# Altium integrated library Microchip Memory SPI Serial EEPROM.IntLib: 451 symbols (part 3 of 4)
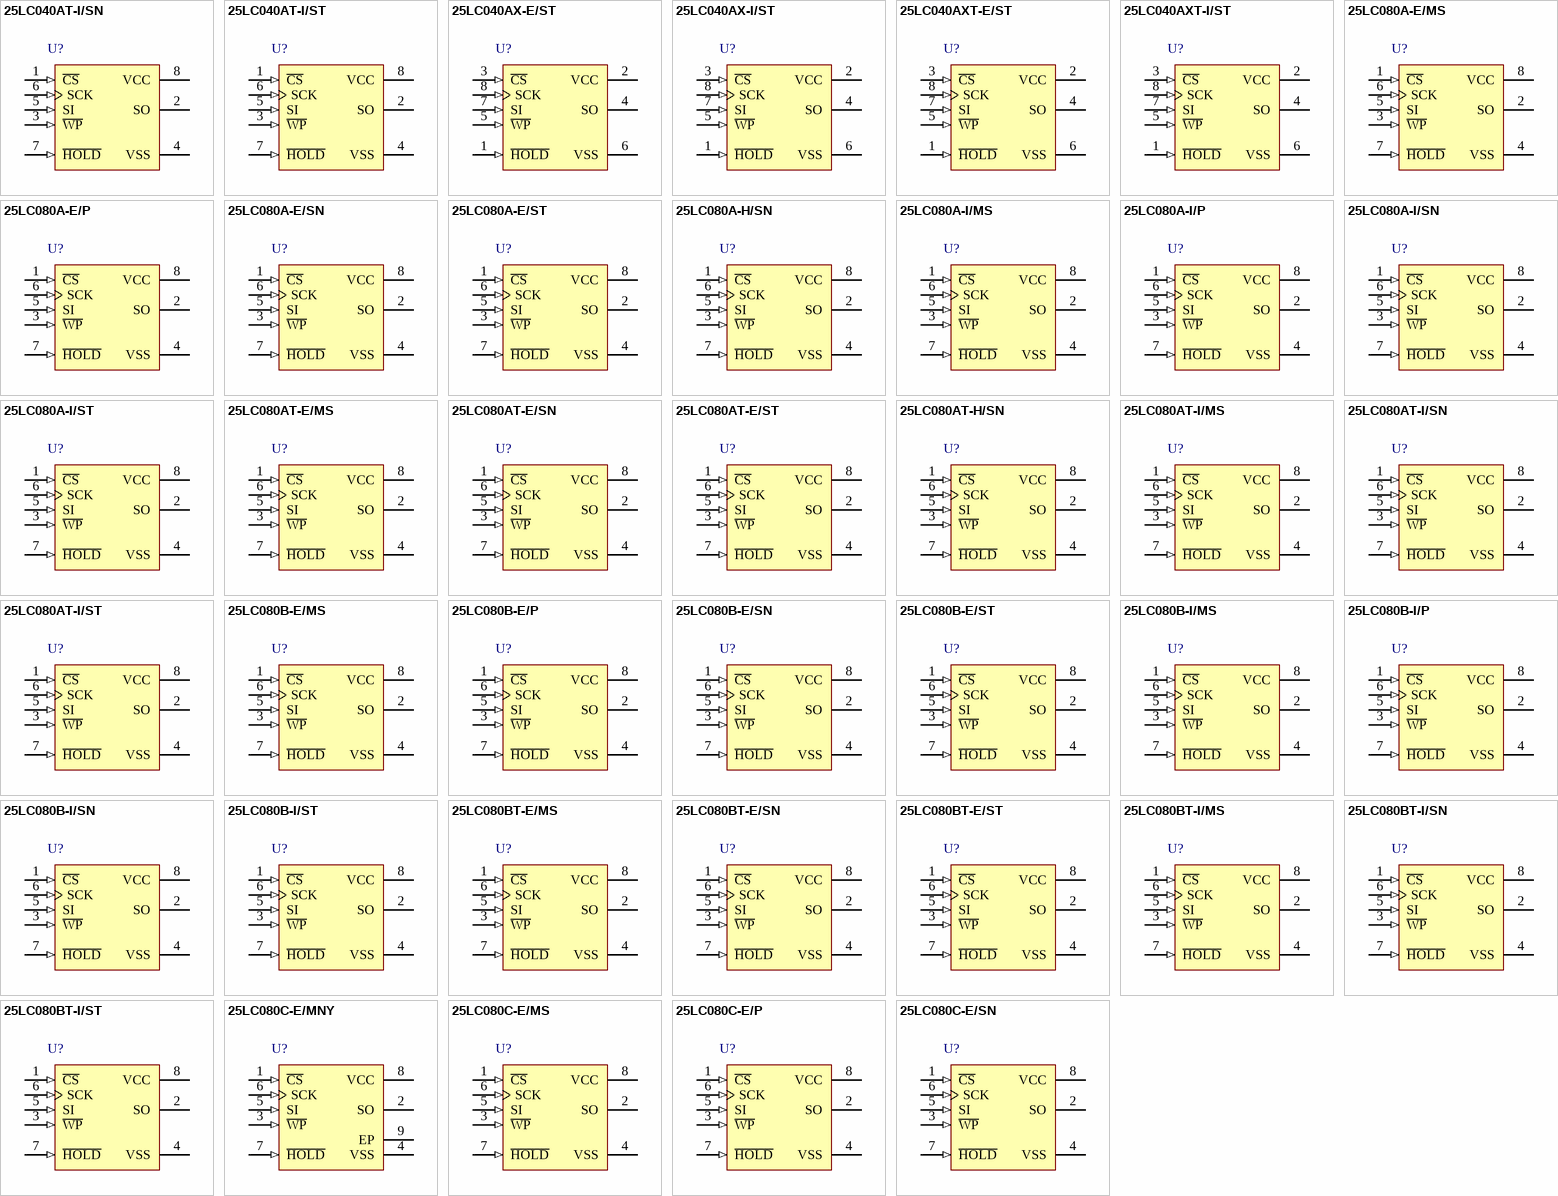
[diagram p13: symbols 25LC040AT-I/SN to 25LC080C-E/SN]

## 25LC080B-E/SN
designator U?
8K SPI Bus Serial EEPROM, 8-Pin SOIC, Extended Temperature; ComponentAvailability: Unknown. Contact manufacturer to determine status.
footprint SOIC-SN8_N (SOIC, 8-Leads, Body 4.9x3.8mm, Pitch 1.27mm, IPC Medium Density)
footprint SOIC-SN8_L (SOIC, 8-Leads, Body 4.9x3.8mm, Pitch 1.27mm, IPC High Density)
footprint SOIC-SN8_M (SOIC, 8-Leads, Body 4.9x3.8mm, Pitch 1.27mm, IPC Low Density)
pins: 1 ~{CS} (in), 2 SO (hiz), 3 ~{WP} (in), 4 VSS (power), 5 SI (in), 6 SCK (in), 7 ~{HOLD} (in), 8 VCC (power)

## 25LC080B-E/ST
designator U?
8K SPI Bus Serial EEPROM, 8-Pin TSSOP, Extended Temperature; ComponentAvailability: Unknown. Contact manufacturer to determine status.
footprint TSSOP-ST8_N (TSOP, 8-Leads, Body 3x4.4mm, Pitch 0.65mm, IPC Medium Density)
footprint TSSOP-ST8_L (TSOP, 8-Leads, Body 3x4.4mm, Pitch 0.65mm, IPC High Density)
footprint TSSOP-ST8_M (TSOP, 8-Leads, Body 3x4.4mm, Pitch 0.65mm, IPC Low Density)
pins: 1 ~{CS} (in), 2 SO (hiz), 3 ~{WP} (in), 4 VSS (power), 5 SI (in), 6 SCK (in), 7 ~{HOLD} (in), 8 VCC (power)

## 25LC080B-I/MS
designator U?
8K SPI Bus Serial EEPROM, 8-Pin MSOP, Industrial Temperature; ComponentAvailability: Unknown. Contact manufacturer to determine status.
footprint MSOP-MS8_N (TSOP, 8-Leads, Body 3x3mm, Pitch 0.65mm, IPC Medium Density)
footprint MSOP-MS8_L (TSOP, 8-Leads, Body 3x3mm, Pitch 0.65mm, IPC High Density)
footprint MSOP-MS8_M (TSOP, 8-Leads, Body 3x3mm, Pitch 0.65mm, IPC Low Density)
pins: 1 ~{CS} (in), 2 SO (hiz), 3 ~{WP} (in), 4 VSS (power), 5 SI (in), 6 SCK (in), 7 ~{HOLD} (in), 8 VCC (power)

## 25LC080B-I/P
designator U?
8K SPI Bus Serial EEPROM, 8-Pin PDIP, Industrial Temperature; ComponentAvailability: Unknown. Contact manufacturer to determine status.
footprint PDIP300-P8 (DIP, 8-Leads, Row Spacing 7.62mm, Pitch 2.54mm, Body 9.5x6.6mm)
pins: 1 ~{CS} (in), 2 SO (hiz), 3 ~{WP} (in), 4 VSS (power), 5 SI (in), 6 SCK (in), 7 ~{HOLD} (in), 8 VCC (power)

## 25LC080B-I/SN
designator U?
8K SPI Bus Serial EEPROM, 8-Pin SOIC, Industrial Temperature; ComponentAvailability: Unknown. Contact manufacturer to determine status.
footprint SOIC-SN8_N (SOIC, 8-Leads, Body 4.9x3.8mm, Pitch 1.27mm, IPC Medium Density)
footprint SOIC-SN8_L (SOIC, 8-Leads, Body 4.9x3.8mm, Pitch 1.27mm, IPC High Density)
footprint SOIC-SN8_M (SOIC, 8-Leads, Body 4.9x3.8mm, Pitch 1.27mm, IPC Low Density)
pins: 1 ~{CS} (in), 2 SO (hiz), 3 ~{WP} (in), 4 VSS (power), 5 SI (in), 6 SCK (in), 7 ~{HOLD} (in), 8 VCC (power)

## 25LC080B-I/ST
designator U?
8K SPI Bus Serial EEPROM, 8-Pin TSSOP, Industrial Temperature; ComponentAvailability: Unknown. Contact manufacturer to determine status.
footprint TSSOP-ST8_N (TSOP, 8-Leads, Body 3x4.4mm, Pitch 0.65mm, IPC Medium Density)
footprint TSSOP-ST8_L (TSOP, 8-Leads, Body 3x4.4mm, Pitch 0.65mm, IPC High Density)
footprint TSSOP-ST8_M (TSOP, 8-Leads, Body 3x4.4mm, Pitch 0.65mm, IPC Low Density)
pins: 1 ~{CS} (in), 2 SO (hiz), 3 ~{WP} (in), 4 VSS (power), 5 SI (in), 6 SCK (in), 7 ~{HOLD} (in), 8 VCC (power)

## 25LC080BT-E/MS
designator U?
8K SPI Bus Serial EEPROM, 8-Pin MSOP, Extended Temperature, Tape and Reel; ComponentAvailability: Unknown. Contact manufacturer to determine status.
footprint MSOP-MS8_N (TSOP, 8-Leads, Body 3x3mm, Pitch 0.65mm, IPC Medium Density)
footprint MSOP-MS8_L (TSOP, 8-Leads, Body 3x3mm, Pitch 0.65mm, IPC High Density)
footprint MSOP-MS8_M (TSOP, 8-Leads, Body 3x3mm, Pitch 0.65mm, IPC Low Density)
pins: 1 ~{CS} (in), 2 SO (hiz), 3 ~{WP} (in), 4 VSS (power), 5 SI (in), 6 SCK (in), 7 ~{HOLD} (in), 8 VCC (power)

## 25LC080BT-E/SN
designator U?
8K SPI Bus Serial EEPROM, 8-Pin SOIC, Extended Temperature, Tape and Reel; ComponentAvailability: Unknown. Contact manufacturer to determine status.
footprint SOIC-SN8_N (SOIC, 8-Leads, Body 4.9x3.8mm, Pitch 1.27mm, IPC Medium Density)
footprint SOIC-SN8_L (SOIC, 8-Leads, Body 4.9x3.8mm, Pitch 1.27mm, IPC High Density)
footprint SOIC-SN8_M (SOIC, 8-Leads, Body 4.9x3.8mm, Pitch 1.27mm, IPC Low Density)
pins: 1 ~{CS} (in), 2 SO (hiz), 3 ~{WP} (in), 4 VSS (power), 5 SI (in), 6 SCK (in), 7 ~{HOLD} (in), 8 VCC (power)

## 25LC080BT-E/ST
designator U?
8K SPI Bus Serial EEPROM, 8-Pin TSSOP, Extended Temperature, Tape and Reel; ComponentAvailability: Unknown. Contact manufacturer to determine status.
footprint TSSOP-ST8_N (TSOP, 8-Leads, Body 3x4.4mm, Pitch 0.65mm, IPC Medium Density)
footprint TSSOP-ST8_L (TSOP, 8-Leads, Body 3x4.4mm, Pitch 0.65mm, IPC High Density)
footprint TSSOP-ST8_M (TSOP, 8-Leads, Body 3x4.4mm, Pitch 0.65mm, IPC Low Density)
pins: 1 ~{CS} (in), 2 SO (hiz), 3 ~{WP} (in), 4 VSS (power), 5 SI (in), 6 SCK (in), 7 ~{HOLD} (in), 8 VCC (power)

## 25LC080BT-I/MS
designator U?
8K SPI Bus Serial EEPROM, 8-Pin MSOP, Industrial Temperature, Tape and Reel; ComponentAvailability: Unknown. Contact manufacturer to determine status.
footprint MSOP-MS8_N (TSOP, 8-Leads, Body 3x3mm, Pitch 0.65mm, IPC Medium Density)
footprint MSOP-MS8_L (TSOP, 8-Leads, Body 3x3mm, Pitch 0.65mm, IPC High Density)
footprint MSOP-MS8_M (TSOP, 8-Leads, Body 3x3mm, Pitch 0.65mm, IPC Low Density)
pins: 1 ~{CS} (in), 2 SO (hiz), 3 ~{WP} (in), 4 VSS (power), 5 SI (in), 6 SCK (in), 7 ~{HOLD} (in), 8 VCC (power)

## 25LC080BT-I/SN
designator U?
8K SPI Bus Serial EEPROM, 8-Pin SOIC, Industrial Temperature, Tape and Reel; ComponentAvailability: Unknown. Contact manufacturer to determine status.
footprint SOIC-SN8_N (SOIC, 8-Leads, Body 4.9x3.8mm, Pitch 1.27mm, IPC Medium Density)
footprint SOIC-SN8_L (SOIC, 8-Leads, Body 4.9x3.8mm, Pitch 1.27mm, IPC High Density)
footprint SOIC-SN8_M (SOIC, 8-Leads, Body 4.9x3.8mm, Pitch 1.27mm, IPC Low Density)
pins: 1 ~{CS} (in), 2 SO (hiz), 3 ~{WP} (in), 4 VSS (power), 5 SI (in), 6 SCK (in), 7 ~{HOLD} (in), 8 VCC (power)

## 25LC080BT-I/ST
designator U?
8K SPI Bus Serial EEPROM, 8-Pin TSSOP, Industrial Temperature, Tape and Reel; ComponentAvailability: Unknown. Contact manufacturer to determine status.
footprint TSSOP-ST8_N (TSOP, 8-Leads, Body 3x4.4mm, Pitch 0.65mm, IPC Medium Density)
footprint TSSOP-ST8_L (TSOP, 8-Leads, Body 3x4.4mm, Pitch 0.65mm, IPC High Density)
footprint TSSOP-ST8_M (TSOP, 8-Leads, Body 3x4.4mm, Pitch 0.65mm, IPC Low Density)
pins: 1 ~{CS} (in), 2 SO (hiz), 3 ~{WP} (in), 4 VSS (power), 5 SI (in), 6 SCK (in), 7 ~{HOLD} (in), 8 VCC (power)

## 25LC080C-E/MNY
designator U?
8K SPI Bus Serial EEPROM, 8-Pin TDFN, Automotive Temperature
footprint TDFN-MN8 (SON, 8-Leads, Body 2x3mm, Pitch 0.5mm, Microchip Recommended)
pins: 1 ~{CS} (in), 2 SO (hiz), 3 ~{WP} (in), 4 VSS (power), 5 SI (in), 6 SCK (in), 7 ~{HOLD} (in), 8 VCC (power), 9 EP

## 25LC080C-E/MS
designator U?
8K SPI Bus Serial EEPROM, 8-Pin MSOP, Automotive Temperature
footprint MSOP-MS8_N (TSOP, 8-Leads, Body 3x3mm, Pitch 0.65mm, IPC Medium Density)
footprint MSOP-MS8_L (TSOP, 8-Leads, Body 3x3mm, Pitch 0.65mm, IPC High Density)
footprint MSOP-MS8_M (TSOP, 8-Leads, Body 3x3mm, Pitch 0.65mm, IPC Low Density)
pins: 1 ~{CS} (in), 2 SO (hiz), 3 ~{WP} (in), 4 VSS (power), 5 SI (in), 6 SCK (in), 7 ~{HOLD} (in), 8 VCC (power)

## 25LC080C-E/P
designator U?
8K SPI Bus Serial EEPROM, 8-Pin PDIP, Automotive Temperature
footprint PDIP300-P8 (DIP, 8-Leads, Row Spacing 7.62mm, Pitch 2.54mm, Body 9.5x6.6mm)
pins: 1 ~{CS} (in), 2 SO (hiz), 3 ~{WP} (in), 4 VSS (power), 5 SI (in), 6 SCK (in), 7 ~{HOLD} (in), 8 VCC (power)

## 25LC080C-E/SN
designator U?
8K SPI Bus Serial EEPROM, 8-Pin SOIC, Automotive Temperature
footprint SOIC-SN8_N (SOIC, 8-Leads, Body 4.9x3.8mm, Pitch 1.27mm, IPC Medium Density)
footprint SOIC-SN8_L (SOIC, 8-Leads, Body 4.9x3.8mm, Pitch 1.27mm, IPC High Density)
footprint SOIC-SN8_M (SOIC, 8-Leads, Body 4.9x3.8mm, Pitch 1.27mm, IPC Low Density)
pins: 1 ~{CS} (in), 2 SO (hiz), 3 ~{WP} (in), 4 VSS (power), 5 SI (in), 6 SCK (in), 7 ~{HOLD} (in), 8 VCC (power)

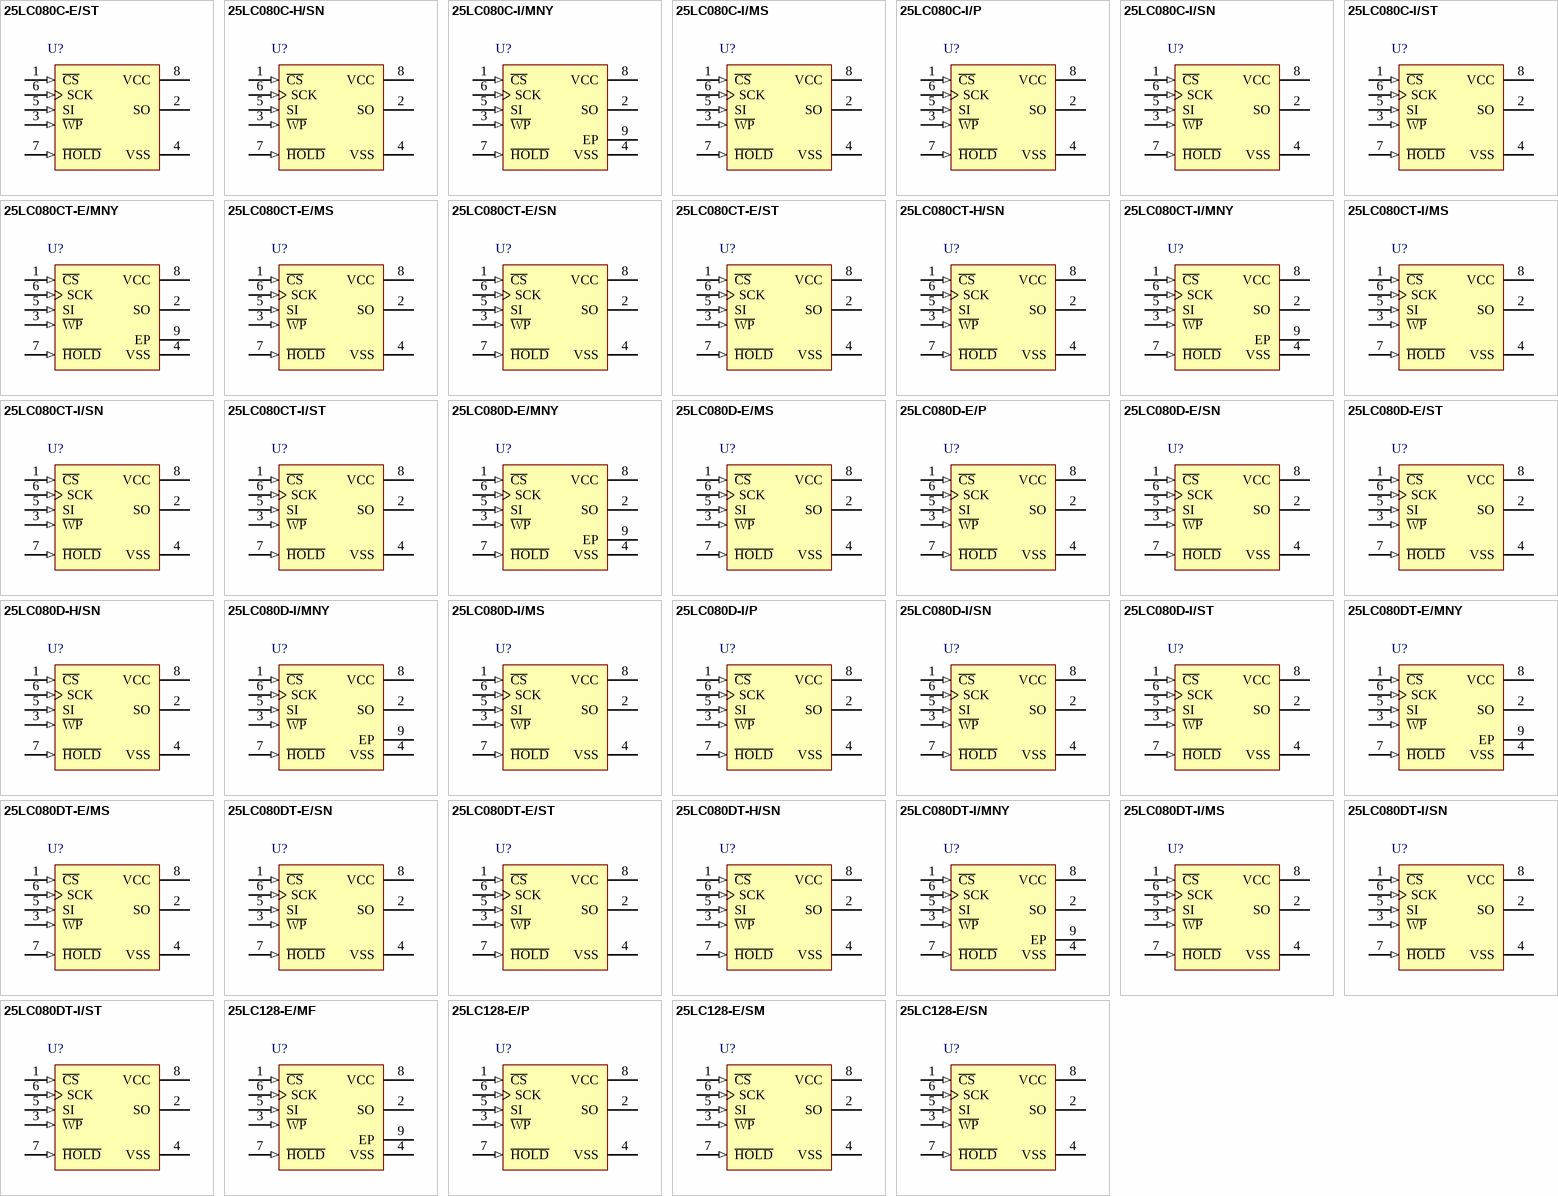
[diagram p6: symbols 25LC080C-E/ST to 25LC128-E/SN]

## 25LC080C-E/ST
designator U?
8K SPI Bus Serial EEPROM, 8-Pin TSSOP, Automotive Temperature
footprint TSSOP-ST8_N (TSOP, 8-Leads, Body 3x4.4mm, Pitch 0.65mm, IPC Medium Density)
footprint TSSOP-ST8_L (TSOP, 8-Leads, Body 3x4.4mm, Pitch 0.65mm, IPC High Density)
footprint TSSOP-ST8_M (TSOP, 8-Leads, Body 3x4.4mm, Pitch 0.65mm, IPC Low Density)
pins: 1 ~{CS} (in), 2 SO (hiz), 3 ~{WP} (in), 4 VSS (power), 5 SI (in), 6 SCK (in), 7 ~{HOLD} (in), 8 VCC (power)

## 25LC080C-H/SN
designator U?
8K SPI Bus Serial EEPROM, 8-Pin SOIC, Extended (High) Temperature
footprint SOIC-SN8_N (SOIC, 8-Leads, Body 4.9x3.8mm, Pitch 1.27mm, IPC Medium Density)
footprint SOIC-SN8_L (SOIC, 8-Leads, Body 4.9x3.8mm, Pitch 1.27mm, IPC High Density)
footprint SOIC-SN8_M (SOIC, 8-Leads, Body 4.9x3.8mm, Pitch 1.27mm, IPC Low Density)
pins: 1 ~{CS} (in), 2 SO (hiz), 3 ~{WP} (in), 4 VSS (power), 5 SI (in), 6 SCK (in), 7 ~{HOLD} (in), 8 VCC (power)

## 25LC080C-I/MNY
designator U?
8K SPI Bus Serial EEPROM, 8-Pin TDFN, Industrial Temperature
footprint TDFN-MN8 (SON, 8-Leads, Body 2x3mm, Pitch 0.5mm, Microchip Recommended)
pins: 1 ~{CS} (in), 2 SO (hiz), 3 ~{WP} (in), 4 VSS (power), 5 SI (in), 6 SCK (in), 7 ~{HOLD} (in), 8 VCC (power), 9 EP

## 25LC080C-I/MS
designator U?
8K SPI Bus Serial EEPROM, 8-Pin MSOP, Industrial Temperature
footprint MSOP-MS8_N (TSOP, 8-Leads, Body 3x3mm, Pitch 0.65mm, IPC Medium Density)
footprint MSOP-MS8_L (TSOP, 8-Leads, Body 3x3mm, Pitch 0.65mm, IPC High Density)
footprint MSOP-MS8_M (TSOP, 8-Leads, Body 3x3mm, Pitch 0.65mm, IPC Low Density)
pins: 1 ~{CS} (in), 2 SO (hiz), 3 ~{WP} (in), 4 VSS (power), 5 SI (in), 6 SCK (in), 7 ~{HOLD} (in), 8 VCC (power)

## 25LC080C-I/P
designator U?
8K SPI Bus Serial EEPROM, 8-Pin PDIP, Industrial Temperature
footprint PDIP300-P8 (DIP, 8-Leads, Row Spacing 7.62mm, Pitch 2.54mm, Body 9.5x6.6mm)
pins: 1 ~{CS} (in), 2 SO (hiz), 3 ~{WP} (in), 4 VSS (power), 5 SI (in), 6 SCK (in), 7 ~{HOLD} (in), 8 VCC (power)

## 25LC080C-I/SN
designator U?
8K SPI Bus Serial EEPROM, 8-Pin SOIC, Industrial Temperature
footprint SOIC-SN8_N (SOIC, 8-Leads, Body 4.9x3.8mm, Pitch 1.27mm, IPC Medium Density)
footprint SOIC-SN8_L (SOIC, 8-Leads, Body 4.9x3.8mm, Pitch 1.27mm, IPC High Density)
footprint SOIC-SN8_M (SOIC, 8-Leads, Body 4.9x3.8mm, Pitch 1.27mm, IPC Low Density)
pins: 1 ~{CS} (in), 2 SO (hiz), 3 ~{WP} (in), 4 VSS (power), 5 SI (in), 6 SCK (in), 7 ~{HOLD} (in), 8 VCC (power)

## 25LC080C-I/ST
designator U?
8K SPI Bus Serial EEPROM, 8-Pin TSSOP, Industrial Temperature
footprint TSSOP-ST8_N (TSOP, 8-Leads, Body 3x4.4mm, Pitch 0.65mm, IPC Medium Density)
footprint TSSOP-ST8_L (TSOP, 8-Leads, Body 3x4.4mm, Pitch 0.65mm, IPC High Density)
footprint TSSOP-ST8_M (TSOP, 8-Leads, Body 3x4.4mm, Pitch 0.65mm, IPC Low Density)
pins: 1 ~{CS} (in), 2 SO (hiz), 3 ~{WP} (in), 4 VSS (power), 5 SI (in), 6 SCK (in), 7 ~{HOLD} (in), 8 VCC (power)

## 25LC080CT-E/MNY
designator U?
8K SPI Bus Serial EEPROM, 8-Pin TDFN, Automotive Temperature, Tape and Reel
footprint TDFN-MN8 (SON, 8-Leads, Body 2x3mm, Pitch 0.5mm, Microchip Recommended)
pins: 1 ~{CS} (in), 2 SO (hiz), 3 ~{WP} (in), 4 VSS (power), 5 SI (in), 6 SCK (in), 7 ~{HOLD} (in), 8 VCC (power), 9 EP

## 25LC080CT-E/MS
designator U?
8K SPI Bus Serial EEPROM, 8-Pin MSOP, Automotive Temperature, Tape and Reel
footprint MSOP-MS8_N (TSOP, 8-Leads, Body 3x3mm, Pitch 0.65mm, IPC Medium Density)
footprint MSOP-MS8_L (TSOP, 8-Leads, Body 3x3mm, Pitch 0.65mm, IPC High Density)
footprint MSOP-MS8_M (TSOP, 8-Leads, Body 3x3mm, Pitch 0.65mm, IPC Low Density)
pins: 1 ~{CS} (in), 2 SO (hiz), 3 ~{WP} (in), 4 VSS (power), 5 SI (in), 6 SCK (in), 7 ~{HOLD} (in), 8 VCC (power)

## 25LC080CT-E/SN
designator U?
8K SPI Bus Serial EEPROM, 8-Pin SOIC, Automotive Temperature, Tape and Reel
footprint SOIC-SN8_N (SOIC, 8-Leads, Body 4.9x3.8mm, Pitch 1.27mm, IPC Medium Density)
footprint SOIC-SN8_L (SOIC, 8-Leads, Body 4.9x3.8mm, Pitch 1.27mm, IPC High Density)
footprint SOIC-SN8_M (SOIC, 8-Leads, Body 4.9x3.8mm, Pitch 1.27mm, IPC Low Density)
pins: 1 ~{CS} (in), 2 SO (hiz), 3 ~{WP} (in), 4 VSS (power), 5 SI (in), 6 SCK (in), 7 ~{HOLD} (in), 8 VCC (power)

## 25LC080CT-E/ST
designator U?
8K SPI Bus Serial EEPROM, 8-Pin TSSOP, Automotive Temperature, Tape and Reel
footprint TSSOP-ST8_N (TSOP, 8-Leads, Body 3x4.4mm, Pitch 0.65mm, IPC Medium Density)
footprint TSSOP-ST8_L (TSOP, 8-Leads, Body 3x4.4mm, Pitch 0.65mm, IPC High Density)
footprint TSSOP-ST8_M (TSOP, 8-Leads, Body 3x4.4mm, Pitch 0.65mm, IPC Low Density)
pins: 1 ~{CS} (in), 2 SO (hiz), 3 ~{WP} (in), 4 VSS (power), 5 SI (in), 6 SCK (in), 7 ~{HOLD} (in), 8 VCC (power)

## 25LC080CT-H/SN
designator U?
8K SPI Bus Serial EEPROM, 8-Pin SOIC, Extended (High) Temperature, Tape and Reel
footprint SOIC-SN8_N (SOIC, 8-Leads, Body 4.9x3.8mm, Pitch 1.27mm, IPC Medium Density)
footprint SOIC-SN8_L (SOIC, 8-Leads, Body 4.9x3.8mm, Pitch 1.27mm, IPC High Density)
footprint SOIC-SN8_M (SOIC, 8-Leads, Body 4.9x3.8mm, Pitch 1.27mm, IPC Low Density)
pins: 1 ~{CS} (in), 2 SO (hiz), 3 ~{WP} (in), 4 VSS (power), 5 SI (in), 6 SCK (in), 7 ~{HOLD} (in), 8 VCC (power)

## 25LC080CT-I/MNY
designator U?
8K SPI Bus Serial EEPROM, 8-Pin TDFN, Industrial Temperature, Tape and Reel
footprint TDFN-MN8 (SON, 8-Leads, Body 2x3mm, Pitch 0.5mm, Microchip Recommended)
pins: 1 ~{CS} (in), 2 SO (hiz), 3 ~{WP} (in), 4 VSS (power), 5 SI (in), 6 SCK (in), 7 ~{HOLD} (in), 8 VCC (power), 9 EP

## 25LC080CT-I/MS
designator U?
8K SPI Bus Serial EEPROM, 8-Pin MSOP, Industrial Temperature, Tape and Reel
footprint MSOP-MS8_N (TSOP, 8-Leads, Body 3x3mm, Pitch 0.65mm, IPC Medium Density)
footprint MSOP-MS8_L (TSOP, 8-Leads, Body 3x3mm, Pitch 0.65mm, IPC High Density)
footprint MSOP-MS8_M (TSOP, 8-Leads, Body 3x3mm, Pitch 0.65mm, IPC Low Density)
pins: 1 ~{CS} (in), 2 SO (hiz), 3 ~{WP} (in), 4 VSS (power), 5 SI (in), 6 SCK (in), 7 ~{HOLD} (in), 8 VCC (power)

## 25LC080CT-I/SN
designator U?
8K SPI Bus Serial EEPROM, 8-Pin SOIC, Industrial Temperature, Tape and Reel
footprint SOIC-SN8_N (SOIC, 8-Leads, Body 4.9x3.8mm, Pitch 1.27mm, IPC Medium Density)
footprint SOIC-SN8_L (SOIC, 8-Leads, Body 4.9x3.8mm, Pitch 1.27mm, IPC High Density)
footprint SOIC-SN8_M (SOIC, 8-Leads, Body 4.9x3.8mm, Pitch 1.27mm, IPC Low Density)
pins: 1 ~{CS} (in), 2 SO (hiz), 3 ~{WP} (in), 4 VSS (power), 5 SI (in), 6 SCK (in), 7 ~{HOLD} (in), 8 VCC (power)

## 25LC080CT-I/ST
designator U?
8K SPI Bus Serial EEPROM, 8-Pin TSSOP, Industrial Temperature, Tape and Reel
footprint TSSOP-ST8_N (TSOP, 8-Leads, Body 3x4.4mm, Pitch 0.65mm, IPC Medium Density)
footprint TSSOP-ST8_L (TSOP, 8-Leads, Body 3x4.4mm, Pitch 0.65mm, IPC High Density)
footprint TSSOP-ST8_M (TSOP, 8-Leads, Body 3x4.4mm, Pitch 0.65mm, IPC Low Density)
pins: 1 ~{CS} (in), 2 SO (hiz), 3 ~{WP} (in), 4 VSS (power), 5 SI (in), 6 SCK (in), 7 ~{HOLD} (in), 8 VCC (power)

## 25LC080D-E/MNY
designator U?
8K SPI Bus Serial EEPROM, 8-Pin TDFN, Automotive Temperature
footprint TDFN-MN8 (SON, 8-Leads, Body 2x3mm, Pitch 0.5mm, Microchip Recommended)
pins: 1 ~{CS} (in), 2 SO (hiz), 3 ~{WP} (in), 4 VSS (power), 5 SI (in), 6 SCK (in), 7 ~{HOLD} (in), 8 VCC (power), 9 EP

## 25LC080D-E/MS
designator U?
8K SPI Bus Serial EEPROM, 8-Pin MSOP, Automotive Temperature
footprint MSOP-MS8_N (TSOP, 8-Leads, Body 3x3mm, Pitch 0.65mm, IPC Medium Density)
footprint MSOP-MS8_L (TSOP, 8-Leads, Body 3x3mm, Pitch 0.65mm, IPC High Density)
footprint MSOP-MS8_M (TSOP, 8-Leads, Body 3x3mm, Pitch 0.65mm, IPC Low Density)
pins: 1 ~{CS} (in), 2 SO (hiz), 3 ~{WP} (in), 4 VSS (power), 5 SI (in), 6 SCK (in), 7 ~{HOLD} (in), 8 VCC (power)

## 25LC080D-E/P
designator U?
8K SPI Bus Serial EEPROM, 8-Pin PDIP, Automotive Temperature
footprint PDIP300-P8 (DIP, 8-Leads, Row Spacing 7.62mm, Pitch 2.54mm, Body 9.5x6.6mm)
pins: 1 ~{CS} (in), 2 SO (hiz), 3 ~{WP} (in), 4 VSS (power), 5 SI (in), 6 SCK (in), 7 ~{HOLD} (in), 8 VCC (power)

## 25LC080D-E/SN
designator U?
8K SPI Bus Serial EEPROM, 8-Pin SOIC, Automotive Temperature
footprint SOIC-SN8_N (SOIC, 8-Leads, Body 4.9x3.8mm, Pitch 1.27mm, IPC Medium Density)
footprint SOIC-SN8_L (SOIC, 8-Leads, Body 4.9x3.8mm, Pitch 1.27mm, IPC High Density)
footprint SOIC-SN8_M (SOIC, 8-Leads, Body 4.9x3.8mm, Pitch 1.27mm, IPC Low Density)
pins: 1 ~{CS} (in), 2 SO (hiz), 3 ~{WP} (in), 4 VSS (power), 5 SI (in), 6 SCK (in), 7 ~{HOLD} (in), 8 VCC (power)

## 25LC080D-E/ST
designator U?
8K SPI Bus Serial EEPROM, 8-Pin TSSOP, Automotive Temperature
footprint TSSOP-ST8_N (TSOP, 8-Leads, Body 3x4.4mm, Pitch 0.65mm, IPC Medium Density)
footprint TSSOP-ST8_L (TSOP, 8-Leads, Body 3x4.4mm, Pitch 0.65mm, IPC High Density)
footprint TSSOP-ST8_M (TSOP, 8-Leads, Body 3x4.4mm, Pitch 0.65mm, IPC Low Density)
pins: 1 ~{CS} (in), 2 SO (hiz), 3 ~{WP} (in), 4 VSS (power), 5 SI (in), 6 SCK (in), 7 ~{HOLD} (in), 8 VCC (power)

## 25LC080D-H/SN
designator U?
8K SPI Bus Serial EEPROM, 8-Pin SOIC, Extended (High) Temperature
footprint SOIC-SN8_N (SOIC, 8-Leads, Body 4.9x3.8mm, Pitch 1.27mm, IPC Medium Density)
footprint SOIC-SN8_L (SOIC, 8-Leads, Body 4.9x3.8mm, Pitch 1.27mm, IPC High Density)
footprint SOIC-SN8_M (SOIC, 8-Leads, Body 4.9x3.8mm, Pitch 1.27mm, IPC Low Density)
pins: 1 ~{CS} (in), 2 SO (hiz), 3 ~{WP} (in), 4 VSS (power), 5 SI (in), 6 SCK (in), 7 ~{HOLD} (in), 8 VCC (power)

## 25LC080D-I/MNY
designator U?
8K SPI Bus Serial EEPROM, 8-Pin TDFN, Industrial Temperature
footprint TDFN-MN8 (SON, 8-Leads, Body 2x3mm, Pitch 0.5mm, Microchip Recommended)
pins: 1 ~{CS} (in), 2 SO (hiz), 3 ~{WP} (in), 4 VSS (power), 5 SI (in), 6 SCK (in), 7 ~{HOLD} (in), 8 VCC (power), 9 EP

## 25LC080D-I/MS
designator U?
8K SPI Bus Serial EEPROM, 8-Pin MSOP, Industrial Temperature
footprint MSOP-MS8_N (TSOP, 8-Leads, Body 3x3mm, Pitch 0.65mm, IPC Medium Density)
footprint MSOP-MS8_L (TSOP, 8-Leads, Body 3x3mm, Pitch 0.65mm, IPC High Density)
footprint MSOP-MS8_M (TSOP, 8-Leads, Body 3x3mm, Pitch 0.65mm, IPC Low Density)
pins: 1 ~{CS} (in), 2 SO (hiz), 3 ~{WP} (in), 4 VSS (power), 5 SI (in), 6 SCK (in), 7 ~{HOLD} (in), 8 VCC (power)

## 25LC080D-I/P
designator U?
8K SPI Bus Serial EEPROM, 8-Pin PDIP, Industrial Temperature
footprint PDIP300-P8 (DIP, 8-Leads, Row Spacing 7.62mm, Pitch 2.54mm, Body 9.5x6.6mm)
pins: 1 ~{CS} (in), 2 SO (hiz), 3 ~{WP} (in), 4 VSS (power), 5 SI (in), 6 SCK (in), 7 ~{HOLD} (in), 8 VCC (power)

## 25LC080D-I/SN
designator U?
8K SPI Bus Serial EEPROM, 8-Pin SOIC, Industrial Temperature
footprint SOIC-SN8_N (SOIC, 8-Leads, Body 4.9x3.8mm, Pitch 1.27mm, IPC Medium Density)
footprint SOIC-SN8_L (SOIC, 8-Leads, Body 4.9x3.8mm, Pitch 1.27mm, IPC High Density)
footprint SOIC-SN8_M (SOIC, 8-Leads, Body 4.9x3.8mm, Pitch 1.27mm, IPC Low Density)
pins: 1 ~{CS} (in), 2 SO (hiz), 3 ~{WP} (in), 4 VSS (power), 5 SI (in), 6 SCK (in), 7 ~{HOLD} (in), 8 VCC (power)

## 25LC080D-I/ST
designator U?
8K SPI Bus Serial EEPROM, 8-Pin TSSOP, Industrial Temperature
footprint TSSOP-ST8_N (TSOP, 8-Leads, Body 3x4.4mm, Pitch 0.65mm, IPC Medium Density)
footprint TSSOP-ST8_L (TSOP, 8-Leads, Body 3x4.4mm, Pitch 0.65mm, IPC High Density)
footprint TSSOP-ST8_M (TSOP, 8-Leads, Body 3x4.4mm, Pitch 0.65mm, IPC Low Density)
pins: 1 ~{CS} (in), 2 SO (hiz), 3 ~{WP} (in), 4 VSS (power), 5 SI (in), 6 SCK (in), 7 ~{HOLD} (in), 8 VCC (power)

## 25LC080DT-E/MNY
designator U?
8K SPI Bus Serial EEPROM, 8-Pin TDFN, Automotive Temperature, Tape and Reel
footprint TDFN-MN8 (SON, 8-Leads, Body 2x3mm, Pitch 0.5mm, Microchip Recommended)
pins: 1 ~{CS} (in), 2 SO (hiz), 3 ~{WP} (in), 4 VSS (power), 5 SI (in), 6 SCK (in), 7 ~{HOLD} (in), 8 VCC (power), 9 EP

## 25LC080DT-E/MS
designator U?
8K SPI Bus Serial EEPROM, 8-Pin MSOP, Automotive Temperature, Tape and Reel
footprint MSOP-MS8_N (TSOP, 8-Leads, Body 3x3mm, Pitch 0.65mm, IPC Medium Density)
footprint MSOP-MS8_L (TSOP, 8-Leads, Body 3x3mm, Pitch 0.65mm, IPC High Density)
footprint MSOP-MS8_M (TSOP, 8-Leads, Body 3x3mm, Pitch 0.65mm, IPC Low Density)
pins: 1 ~{CS} (in), 2 SO (hiz), 3 ~{WP} (in), 4 VSS (power), 5 SI (in), 6 SCK (in), 7 ~{HOLD} (in), 8 VCC (power)

## 25LC080DT-E/SN
designator U?
8K SPI Bus Serial EEPROM, 8-Pin SOIC, Automotive Temperature, Tape and Reel
footprint SOIC-SN8_N (SOIC, 8-Leads, Body 4.9x3.8mm, Pitch 1.27mm, IPC Medium Density)
footprint SOIC-SN8_L (SOIC, 8-Leads, Body 4.9x3.8mm, Pitch 1.27mm, IPC High Density)
footprint SOIC-SN8_M (SOIC, 8-Leads, Body 4.9x3.8mm, Pitch 1.27mm, IPC Low Density)
pins: 1 ~{CS} (in), 2 SO (hiz), 3 ~{WP} (in), 4 VSS (power), 5 SI (in), 6 SCK (in), 7 ~{HOLD} (in), 8 VCC (power)

## 25LC080DT-E/ST
designator U?
8K SPI Bus Serial EEPROM, 8-Pin TSSOP, Automotive Temperature, Tape and Reel
footprint TSSOP-ST8_N (TSOP, 8-Leads, Body 3x4.4mm, Pitch 0.65mm, IPC Medium Density)
footprint TSSOP-ST8_L (TSOP, 8-Leads, Body 3x4.4mm, Pitch 0.65mm, IPC High Density)
footprint TSSOP-ST8_M (TSOP, 8-Leads, Body 3x4.4mm, Pitch 0.65mm, IPC Low Density)
pins: 1 ~{CS} (in), 2 SO (hiz), 3 ~{WP} (in), 4 VSS (power), 5 SI (in), 6 SCK (in), 7 ~{HOLD} (in), 8 VCC (power)

## 25LC080DT-H/SN
designator U?
8K SPI Bus Serial EEPROM, 8-Pin SOIC, Extended (High) Temperature, Tape and Reel
footprint SOIC-SN8_N (SOIC, 8-Leads, Body 4.9x3.8mm, Pitch 1.27mm, IPC Medium Density)
footprint SOIC-SN8_L (SOIC, 8-Leads, Body 4.9x3.8mm, Pitch 1.27mm, IPC High Density)
footprint SOIC-SN8_M (SOIC, 8-Leads, Body 4.9x3.8mm, Pitch 1.27mm, IPC Low Density)
pins: 1 ~{CS} (in), 2 SO (hiz), 3 ~{WP} (in), 4 VSS (power), 5 SI (in), 6 SCK (in), 7 ~{HOLD} (in), 8 VCC (power)

## 25LC080DT-I/MNY
designator U?
8K SPI Bus Serial EEPROM, 8-Pin TDFN, Industrial Temperature, Tape and Reel
footprint TDFN-MN8 (SON, 8-Leads, Body 2x3mm, Pitch 0.5mm, Microchip Recommended)
pins: 1 ~{CS} (in), 2 SO (hiz), 3 ~{WP} (in), 4 VSS (power), 5 SI (in), 6 SCK (in), 7 ~{HOLD} (in), 8 VCC (power), 9 EP

## 25LC080DT-I/MS
designator U?
8K SPI Bus Serial EEPROM, 8-Pin MSOP, Industrial Temperature, Tape and Reel
footprint MSOP-MS8_N (TSOP, 8-Leads, Body 3x3mm, Pitch 0.65mm, IPC Medium Density)
footprint MSOP-MS8_L (TSOP, 8-Leads, Body 3x3mm, Pitch 0.65mm, IPC High Density)
footprint MSOP-MS8_M (TSOP, 8-Leads, Body 3x3mm, Pitch 0.65mm, IPC Low Density)
pins: 1 ~{CS} (in), 2 SO (hiz), 3 ~{WP} (in), 4 VSS (power), 5 SI (in), 6 SCK (in), 7 ~{HOLD} (in), 8 VCC (power)

## 25LC080DT-I/SN
designator U?
8K SPI Bus Serial EEPROM, 8-Pin SOIC, Industrial Temperature, Tape and Reel
footprint SOIC-SN8_N (SOIC, 8-Leads, Body 4.9x3.8mm, Pitch 1.27mm, IPC Medium Density)
footprint SOIC-SN8_L (SOIC, 8-Leads, Body 4.9x3.8mm, Pitch 1.27mm, IPC High Density)
footprint SOIC-SN8_M (SOIC, 8-Leads, Body 4.9x3.8mm, Pitch 1.27mm, IPC Low Density)
pins: 1 ~{CS} (in), 2 SO (hiz), 3 ~{WP} (in), 4 VSS (power), 5 SI (in), 6 SCK (in), 7 ~{HOLD} (in), 8 VCC (power)

## 25LC080DT-I/ST
designator U?
8K SPI Bus Serial EEPROM, 8-Pin TSSOP, Industrial Temperature, Tape and Reel
footprint TSSOP-ST8_N (TSOP, 8-Leads, Body 3x4.4mm, Pitch 0.65mm, IPC Medium Density)
footprint TSSOP-ST8_L (TSOP, 8-Leads, Body 3x4.4mm, Pitch 0.65mm, IPC High Density)
footprint TSSOP-ST8_M (TSOP, 8-Leads, Body 3x4.4mm, Pitch 0.65mm, IPC Low Density)
pins: 1 ~{CS} (in), 2 SO (hiz), 3 ~{WP} (in), 4 VSS (power), 5 SI (in), 6 SCK (in), 7 ~{HOLD} (in), 8 VCC (power)

## 25LC128-E/MF
designator U?
128K SPI Bus Serial EEPROM, 8-Pin DFN, Extended Temperature
footprint DFNS-MF8_PS (SON, 8-Leads, Body 5x6mm, Pitch 1.27mm)
pins: 1 ~{CS} (in), 2 SO (hiz), 3 ~{WP} (in), 4 VSS (power), 5 SI (in), 6 SCK (in), 7 ~{HOLD} (in), 8 VCC (power), 9 EP

## 25LC128-E/P
designator U?
128K SPI Bus Serial EEPROM, 8-Pin PDIP, Extended Temperature
footprint PDIP300-P8 (DIP, 8-Leads, Row Spacing 7.62mm, Pitch 2.54mm, Body 9.5x6.6mm)
pins: 1 ~{CS} (in), 2 SO (hiz), 3 ~{WP} (in), 4 VSS (power), 5 SI (in), 6 SCK (in), 7 ~{HOLD} (in), 8 VCC (power)

## 25LC128-E/SM
designator U?
128K SPI Bus Serial EEPROM, 8-Pin SOIJ, Extended Temperature
footprint SOIJ-SM8_N (SOP, 8-Leads, Body 5.2x5.2mm, Pitch 1.27mm, IPC Medium Density)
footprint SOIJ-SM8_L (SOP, 8-Leads, Body 5.2x5.2mm, Pitch 1.27mm, IPC High Density)
footprint SOIJ-SM8_M (SOP, 8-Leads, Body 5.2x5.2mm, Pitch 1.27mm, IPC Low Density)
pins: 1 ~{CS} (in), 2 SO (hiz), 3 ~{WP} (in), 4 VSS (power), 5 SI (in), 6 SCK (in), 7 ~{HOLD} (in), 8 VCC (power)

## 25LC128-E/SN
designator U?
128K SPI Bus Serial EEPROM, 8-Pin SOIC, Extended Temperature
footprint SOIC-SN8_N (SOIC, 8-Leads, Body 4.9x3.8mm, Pitch 1.27mm, IPC Medium Density)
footprint SOIC-SN8_L (SOIC, 8-Leads, Body 4.9x3.8mm, Pitch 1.27mm, IPC High Density)
footprint SOIC-SN8_M (SOIC, 8-Leads, Body 4.9x3.8mm, Pitch 1.27mm, IPC Low Density)
pins: 1 ~{CS} (in), 2 SO (hiz), 3 ~{WP} (in), 4 VSS (power), 5 SI (in), 6 SCK (in), 7 ~{HOLD} (in), 8 VCC (power)

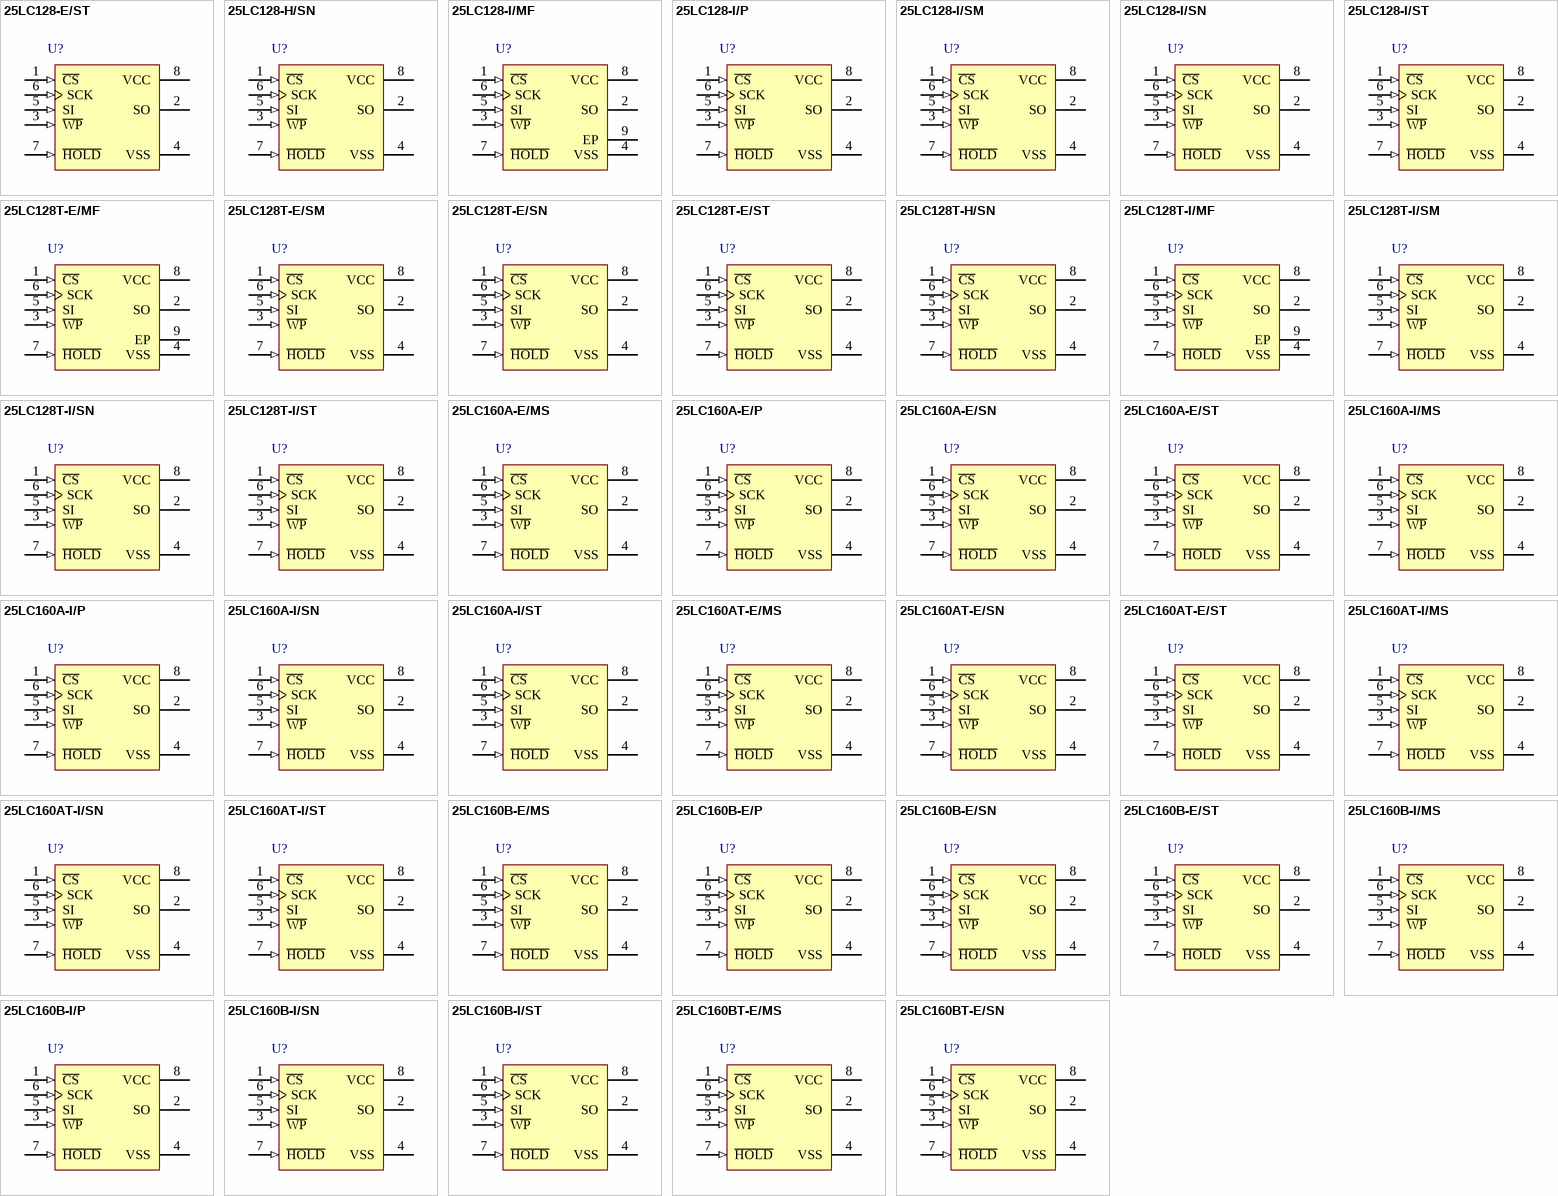
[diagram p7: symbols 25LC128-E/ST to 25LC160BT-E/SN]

## 25LC128-E/ST
designator U?
128K SPI Bus Serial EEPROM, 8-Pin TSSOP, Extended Temperature
footprint TSSOP-ST8_N (TSOP, 8-Leads, Body 3x4.4mm, Pitch 0.65mm, IPC Medium Density)
footprint TSSOP-ST8_L (TSOP, 8-Leads, Body 3x4.4mm, Pitch 0.65mm, IPC High Density)
footprint TSSOP-ST8_M (TSOP, 8-Leads, Body 3x4.4mm, Pitch 0.65mm, IPC Low Density)
pins: 1 ~{CS} (in), 2 SO (hiz), 3 ~{WP} (in), 4 VSS (power), 5 SI (in), 6 SCK (in), 7 ~{HOLD} (in), 8 VCC (power)

## 25LC128-H/SN
designator U?
128K SPI Bus Serial EEPROM, 8-Pin SOIC, Extended (High) Temperature
footprint SOIC-SN8_N (SOIC, 8-Leads, Body 4.9x3.8mm, Pitch 1.27mm, IPC Medium Density)
footprint SOIC-SN8_L (SOIC, 8-Leads, Body 4.9x3.8mm, Pitch 1.27mm, IPC High Density)
footprint SOIC-SN8_M (SOIC, 8-Leads, Body 4.9x3.8mm, Pitch 1.27mm, IPC Low Density)
pins: 1 ~{CS} (in), 2 SO (hiz), 3 ~{WP} (in), 4 VSS (power), 5 SI (in), 6 SCK (in), 7 ~{HOLD} (in), 8 VCC (power)

## 25LC128-I/MF
designator U?
128K SPI Bus Serial EEPROM, 8-Pin DFN, Industrial Temperature
footprint DFNS-MF8_PS (SON, 8-Leads, Body 5x6mm, Pitch 1.27mm)
pins: 1 ~{CS} (in), 2 SO (hiz), 3 ~{WP} (in), 4 VSS (power), 5 SI (in), 6 SCK (in), 7 ~{HOLD} (in), 8 VCC (power), 9 EP

## 25LC128-I/P
designator U?
128K SPI Bus Serial EEPROM, 8-Pin PDIP, Industrial Temperature
footprint PDIP300-P8 (DIP, 8-Leads, Row Spacing 7.62mm, Pitch 2.54mm, Body 9.5x6.6mm)
pins: 1 ~{CS} (in), 2 SO (hiz), 3 ~{WP} (in), 4 VSS (power), 5 SI (in), 6 SCK (in), 7 ~{HOLD} (in), 8 VCC (power)

## 25LC128-I/SM
designator U?
128K SPI Bus Serial EEPROM, 8-Pin SOIJ, Industrial Temperature
footprint SOIJ-SM8_N (SOP, 8-Leads, Body 5.2x5.2mm, Pitch 1.27mm, IPC Medium Density)
footprint SOIJ-SM8_L (SOP, 8-Leads, Body 5.2x5.2mm, Pitch 1.27mm, IPC High Density)
footprint SOIJ-SM8_M (SOP, 8-Leads, Body 5.2x5.2mm, Pitch 1.27mm, IPC Low Density)
pins: 1 ~{CS} (in), 2 SO (hiz), 3 ~{WP} (in), 4 VSS (power), 5 SI (in), 6 SCK (in), 7 ~{HOLD} (in), 8 VCC (power)

## 25LC128-I/SN
designator U?
128K SPI Bus Serial EEPROM, 8-Pin SOIC, Industrial Temperature
footprint SOIC-SN8_N (SOIC, 8-Leads, Body 4.9x3.8mm, Pitch 1.27mm, IPC Medium Density)
footprint SOIC-SN8_L (SOIC, 8-Leads, Body 4.9x3.8mm, Pitch 1.27mm, IPC High Density)
footprint SOIC-SN8_M (SOIC, 8-Leads, Body 4.9x3.8mm, Pitch 1.27mm, IPC Low Density)
pins: 1 ~{CS} (in), 2 SO (hiz), 3 ~{WP} (in), 4 VSS (power), 5 SI (in), 6 SCK (in), 7 ~{HOLD} (in), 8 VCC (power)

## 25LC128-I/ST
designator U?
128K SPI Bus Serial EEPROM, 8-Pin TSSOP, Industrial Temperature
footprint TSSOP-ST8_N (TSOP, 8-Leads, Body 3x4.4mm, Pitch 0.65mm, IPC Medium Density)
footprint TSSOP-ST8_L (TSOP, 8-Leads, Body 3x4.4mm, Pitch 0.65mm, IPC High Density)
footprint TSSOP-ST8_M (TSOP, 8-Leads, Body 3x4.4mm, Pitch 0.65mm, IPC Low Density)
pins: 1 ~{CS} (in), 2 SO (hiz), 3 ~{WP} (in), 4 VSS (power), 5 SI (in), 6 SCK (in), 7 ~{HOLD} (in), 8 VCC (power)

## 25LC128T-E/MF
designator U?
128K SPI Bus Serial EEPROM, 8-Pin DFN, Extended Temperature, Tape and Reel
footprint DFNS-MF8_PS (SON, 8-Leads, Body 5x6mm, Pitch 1.27mm)
pins: 1 ~{CS} (in), 2 SO (hiz), 3 ~{WP} (in), 4 VSS (power), 5 SI (in), 6 SCK (in), 7 ~{HOLD} (in), 8 VCC (power), 9 EP

## 25LC128T-E/SM
designator U?
128K SPI Bus Serial EEPROM, 8-Pin SOIJ, Extended Temperature, Tape and Reel
footprint SOIJ-SM8_N (SOP, 8-Leads, Body 5.2x5.2mm, Pitch 1.27mm, IPC Medium Density)
footprint SOIJ-SM8_L (SOP, 8-Leads, Body 5.2x5.2mm, Pitch 1.27mm, IPC High Density)
footprint SOIJ-SM8_M (SOP, 8-Leads, Body 5.2x5.2mm, Pitch 1.27mm, IPC Low Density)
pins: 1 ~{CS} (in), 2 SO (hiz), 3 ~{WP} (in), 4 VSS (power), 5 SI (in), 6 SCK (in), 7 ~{HOLD} (in), 8 VCC (power)

## 25LC128T-E/SN
designator U?
128K SPI Bus Serial EEPROM, 8-Pin SOIC, Extended Temperature, Tape and Reel
footprint SOIC-SN8_N (SOIC, 8-Leads, Body 4.9x3.8mm, Pitch 1.27mm, IPC Medium Density)
footprint SOIC-SN8_L (SOIC, 8-Leads, Body 4.9x3.8mm, Pitch 1.27mm, IPC High Density)
footprint SOIC-SN8_M (SOIC, 8-Leads, Body 4.9x3.8mm, Pitch 1.27mm, IPC Low Density)
pins: 1 ~{CS} (in), 2 SO (hiz), 3 ~{WP} (in), 4 VSS (power), 5 SI (in), 6 SCK (in), 7 ~{HOLD} (in), 8 VCC (power)

## 25LC128T-E/ST
designator U?
128K SPI Bus Serial EEPROM, 8-Pin TSSOP, Extended Temperature, Tape and Reel
footprint TSSOP-ST8_N (TSOP, 8-Leads, Body 3x4.4mm, Pitch 0.65mm, IPC Medium Density)
footprint TSSOP-ST8_L (TSOP, 8-Leads, Body 3x4.4mm, Pitch 0.65mm, IPC High Density)
footprint TSSOP-ST8_M (TSOP, 8-Leads, Body 3x4.4mm, Pitch 0.65mm, IPC Low Density)
pins: 1 ~{CS} (in), 2 SO (hiz), 3 ~{WP} (in), 4 VSS (power), 5 SI (in), 6 SCK (in), 7 ~{HOLD} (in), 8 VCC (power)

## 25LC128T-H/SN
designator U?
128K SPI Bus Serial EEPROM, 8-Pin SOIC, Extended (High) Temperature, Tape and Reel
footprint SOIC-SN8_N (SOIC, 8-Leads, Body 4.9x3.8mm, Pitch 1.27mm, IPC Medium Density)
footprint SOIC-SN8_L (SOIC, 8-Leads, Body 4.9x3.8mm, Pitch 1.27mm, IPC High Density)
footprint SOIC-SN8_M (SOIC, 8-Leads, Body 4.9x3.8mm, Pitch 1.27mm, IPC Low Density)
pins: 1 ~{CS} (in), 2 SO (hiz), 3 ~{WP} (in), 4 VSS (power), 5 SI (in), 6 SCK (in), 7 ~{HOLD} (in), 8 VCC (power)

## 25LC128T-I/MF
designator U?
128K SPI Bus Serial EEPROM, 8-Pin DFN, Industrial Temperature, Tape and Reel
footprint DFNS-MF8_PS (SON, 8-Leads, Body 5x6mm, Pitch 1.27mm)
pins: 1 ~{CS} (in), 2 SO (hiz), 3 ~{WP} (in), 4 VSS (power), 5 SI (in), 6 SCK (in), 7 ~{HOLD} (in), 8 VCC (power), 9 EP

## 25LC128T-I/SM
designator U?
128K SPI Bus Serial EEPROM, 8-Pin SOIJ, Industrial Temperature, Tape and Reel
footprint SOIJ-SM8_N (SOP, 8-Leads, Body 5.2x5.2mm, Pitch 1.27mm, IPC Medium Density)
footprint SOIJ-SM8_L (SOP, 8-Leads, Body 5.2x5.2mm, Pitch 1.27mm, IPC High Density)
footprint SOIJ-SM8_M (SOP, 8-Leads, Body 5.2x5.2mm, Pitch 1.27mm, IPC Low Density)
pins: 1 ~{CS} (in), 2 SO (hiz), 3 ~{WP} (in), 4 VSS (power), 5 SI (in), 6 SCK (in), 7 ~{HOLD} (in), 8 VCC (power)

## 25LC128T-I/SN
designator U?
128K SPI Bus Serial EEPROM, 8-Pin SOIC, Industrial Temperature, Tape and Reel
footprint SOIC-SN8_N (SOIC, 8-Leads, Body 4.9x3.8mm, Pitch 1.27mm, IPC Medium Density)
footprint SOIC-SN8_L (SOIC, 8-Leads, Body 4.9x3.8mm, Pitch 1.27mm, IPC High Density)
footprint SOIC-SN8_M (SOIC, 8-Leads, Body 4.9x3.8mm, Pitch 1.27mm, IPC Low Density)
pins: 1 ~{CS} (in), 2 SO (hiz), 3 ~{WP} (in), 4 VSS (power), 5 SI (in), 6 SCK (in), 7 ~{HOLD} (in), 8 VCC (power)

## 25LC128T-I/ST
designator U?
128K SPI Bus Serial EEPROM, 8-Pin TSSOP, Industrial Temperature, Tape and Reel
footprint TSSOP-ST8_N (TSOP, 8-Leads, Body 3x4.4mm, Pitch 0.65mm, IPC Medium Density)
footprint TSSOP-ST8_L (TSOP, 8-Leads, Body 3x4.4mm, Pitch 0.65mm, IPC High Density)
footprint TSSOP-ST8_M (TSOP, 8-Leads, Body 3x4.4mm, Pitch 0.65mm, IPC Low Density)
pins: 1 ~{CS} (in), 2 SO (hiz), 3 ~{WP} (in), 4 VSS (power), 5 SI (in), 6 SCK (in), 7 ~{HOLD} (in), 8 VCC (power)

## 25LC160A-E/MS
designator U?
16K SPI Bus Serial EEPROM, 8-Pin MSOP, Extended Temperature; ComponentAvailability: Unknown. Contact manufacturer to determine status.
footprint MSOP-MS8_N (TSOP, 8-Leads, Body 3x3mm, Pitch 0.65mm, IPC Medium Density)
footprint MSOP-MS8_L (TSOP, 8-Leads, Body 3x3mm, Pitch 0.65mm, IPC High Density)
footprint MSOP-MS8_M (TSOP, 8-Leads, Body 3x3mm, Pitch 0.65mm, IPC Low Density)
pins: 1 ~{CS} (in), 2 SO (hiz), 3 ~{WP} (in), 4 VSS (power), 5 SI (in), 6 SCK (in), 7 ~{HOLD} (in), 8 VCC (power)

## 25LC160A-E/P
designator U?
16K SPI Bus Serial EEPROM, 8-Pin PDIP, Extended Temperature; ComponentAvailability: Unknown. Contact manufacturer to determine status.
footprint PDIP300-P8 (DIP, 8-Leads, Row Spacing 7.62mm, Pitch 2.54mm, Body 9.5x6.6mm)
pins: 1 ~{CS} (in), 2 SO (hiz), 3 ~{WP} (in), 4 VSS (power), 5 SI (in), 6 SCK (in), 7 ~{HOLD} (in), 8 VCC (power)

## 25LC160A-E/SN
designator U?
16K SPI Bus Serial EEPROM, 8-Pin SOIC, Extended Temperature; ComponentAvailability: Unknown. Contact manufacturer to determine status.
footprint SOIC-SN8_N (SOIC, 8-Leads, Body 4.9x3.8mm, Pitch 1.27mm, IPC Medium Density)
footprint SOIC-SN8_L (SOIC, 8-Leads, Body 4.9x3.8mm, Pitch 1.27mm, IPC High Density)
footprint SOIC-SN8_M (SOIC, 8-Leads, Body 4.9x3.8mm, Pitch 1.27mm, IPC Low Density)
pins: 1 ~{CS} (in), 2 SO (hiz), 3 ~{WP} (in), 4 VSS (power), 5 SI (in), 6 SCK (in), 7 ~{HOLD} (in), 8 VCC (power)

## 25LC160A-E/ST
designator U?
16K SPI Bus Serial EEPROM, 8-Pin TSSOP, Extended Temperature; ComponentAvailability: Unknown. Contact manufacturer to determine status.
footprint TSSOP-ST8_N (TSOP, 8-Leads, Body 3x4.4mm, Pitch 0.65mm, IPC Medium Density)
footprint TSSOP-ST8_L (TSOP, 8-Leads, Body 3x4.4mm, Pitch 0.65mm, IPC High Density)
footprint TSSOP-ST8_M (TSOP, 8-Leads, Body 3x4.4mm, Pitch 0.65mm, IPC Low Density)
pins: 1 ~{CS} (in), 2 SO (hiz), 3 ~{WP} (in), 4 VSS (power), 5 SI (in), 6 SCK (in), 7 ~{HOLD} (in), 8 VCC (power)

## 25LC160A-I/MS
designator U?
16K SPI Bus Serial EEPROM, 8-Pin MSOP, Industrial Temperature; ComponentAvailability: Unknown. Contact manufacturer to determine status.
footprint MSOP-MS8_N (TSOP, 8-Leads, Body 3x3mm, Pitch 0.65mm, IPC Medium Density)
footprint MSOP-MS8_L (TSOP, 8-Leads, Body 3x3mm, Pitch 0.65mm, IPC High Density)
footprint MSOP-MS8_M (TSOP, 8-Leads, Body 3x3mm, Pitch 0.65mm, IPC Low Density)
pins: 1 ~{CS} (in), 2 SO (hiz), 3 ~{WP} (in), 4 VSS (power), 5 SI (in), 6 SCK (in), 7 ~{HOLD} (in), 8 VCC (power)

## 25LC160A-I/P
designator U?
16K SPI Bus Serial EEPROM, 8-Pin PDIP, Industrial Temperature; ComponentAvailability: Unknown. Contact manufacturer to determine status.
footprint PDIP300-P8 (DIP, 8-Leads, Row Spacing 7.62mm, Pitch 2.54mm, Body 9.5x6.6mm)
pins: 1 ~{CS} (in), 2 SO (hiz), 3 ~{WP} (in), 4 VSS (power), 5 SI (in), 6 SCK (in), 7 ~{HOLD} (in), 8 VCC (power)

## 25LC160A-I/SN
designator U?
16K SPI Bus Serial EEPROM, 8-Pin SOIC, Industrial Temperature; ComponentAvailability: Unknown. Contact manufacturer to determine status.
footprint SOIC-SN8_N (SOIC, 8-Leads, Body 4.9x3.8mm, Pitch 1.27mm, IPC Medium Density)
footprint SOIC-SN8_L (SOIC, 8-Leads, Body 4.9x3.8mm, Pitch 1.27mm, IPC High Density)
footprint SOIC-SN8_M (SOIC, 8-Leads, Body 4.9x3.8mm, Pitch 1.27mm, IPC Low Density)
pins: 1 ~{CS} (in), 2 SO (hiz), 3 ~{WP} (in), 4 VSS (power), 5 SI (in), 6 SCK (in), 7 ~{HOLD} (in), 8 VCC (power)

## 25LC160A-I/ST
designator U?
16K SPI Bus Serial EEPROM, 8-Pin TSSOP, Industrial Temperature; ComponentAvailability: Unknown. Contact manufacturer to determine status.
footprint TSSOP-ST8_N (TSOP, 8-Leads, Body 3x4.4mm, Pitch 0.65mm, IPC Medium Density)
footprint TSSOP-ST8_L (TSOP, 8-Leads, Body 3x4.4mm, Pitch 0.65mm, IPC High Density)
footprint TSSOP-ST8_M (TSOP, 8-Leads, Body 3x4.4mm, Pitch 0.65mm, IPC Low Density)
pins: 1 ~{CS} (in), 2 SO (hiz), 3 ~{WP} (in), 4 VSS (power), 5 SI (in), 6 SCK (in), 7 ~{HOLD} (in), 8 VCC (power)

## 25LC160AT-E/MS
designator U?
16K SPI Bus Serial EEPROM, 8-Pin MSOP, Extended Temperature, Tape and Reel; ComponentAvailability: Unknown. Contact manufacturer to determine status.
footprint MSOP-MS8_N (TSOP, 8-Leads, Body 3x3mm, Pitch 0.65mm, IPC Medium Density)
footprint MSOP-MS8_L (TSOP, 8-Leads, Body 3x3mm, Pitch 0.65mm, IPC High Density)
footprint MSOP-MS8_M (TSOP, 8-Leads, Body 3x3mm, Pitch 0.65mm, IPC Low Density)
pins: 1 ~{CS} (in), 2 SO (hiz), 3 ~{WP} (in), 4 VSS (power), 5 SI (in), 6 SCK (in), 7 ~{HOLD} (in), 8 VCC (power)

## 25LC160AT-E/SN
designator U?
16K SPI Bus Serial EEPROM, 8-Pin SOIC, Extended Temperature, Tape and Reel; ComponentAvailability: Unknown. Contact manufacturer to determine status.
footprint SOIC-SN8_N (SOIC, 8-Leads, Body 4.9x3.8mm, Pitch 1.27mm, IPC Medium Density)
footprint SOIC-SN8_L (SOIC, 8-Leads, Body 4.9x3.8mm, Pitch 1.27mm, IPC High Density)
footprint SOIC-SN8_M (SOIC, 8-Leads, Body 4.9x3.8mm, Pitch 1.27mm, IPC Low Density)
pins: 1 ~{CS} (in), 2 SO (hiz), 3 ~{WP} (in), 4 VSS (power), 5 SI (in), 6 SCK (in), 7 ~{HOLD} (in), 8 VCC (power)

## 25LC160AT-E/ST
designator U?
16K SPI Bus Serial EEPROM, 8-Pin TSSOP, Extended Temperature, Tape and Reel; ComponentAvailability: Unknown. Contact manufacturer to determine status.
footprint TSSOP-ST8_N (TSOP, 8-Leads, Body 3x4.4mm, Pitch 0.65mm, IPC Medium Density)
footprint TSSOP-ST8_L (TSOP, 8-Leads, Body 3x4.4mm, Pitch 0.65mm, IPC High Density)
footprint TSSOP-ST8_M (TSOP, 8-Leads, Body 3x4.4mm, Pitch 0.65mm, IPC Low Density)
pins: 1 ~{CS} (in), 2 SO (hiz), 3 ~{WP} (in), 4 VSS (power), 5 SI (in), 6 SCK (in), 7 ~{HOLD} (in), 8 VCC (power)

## 25LC160AT-I/MS
designator U?
16K SPI Bus Serial EEPROM, 8-Pin MSOP, Industrial Temperature, Tape and Reel; ComponentAvailability: Unknown. Contact manufacturer to determine status.
footprint MSOP-MS8_N (TSOP, 8-Leads, Body 3x3mm, Pitch 0.65mm, IPC Medium Density)
footprint MSOP-MS8_L (TSOP, 8-Leads, Body 3x3mm, Pitch 0.65mm, IPC High Density)
footprint MSOP-MS8_M (TSOP, 8-Leads, Body 3x3mm, Pitch 0.65mm, IPC Low Density)
pins: 1 ~{CS} (in), 2 SO (hiz), 3 ~{WP} (in), 4 VSS (power), 5 SI (in), 6 SCK (in), 7 ~{HOLD} (in), 8 VCC (power)

## 25LC160AT-I/SN
designator U?
16K SPI Bus Serial EEPROM, 8-Pin SOIC, Industrial Temperature, Tape and Reel; ComponentAvailability: Unknown. Contact manufacturer to determine status.
footprint SOIC-SN8_N (SOIC, 8-Leads, Body 4.9x3.8mm, Pitch 1.27mm, IPC Medium Density)
footprint SOIC-SN8_L (SOIC, 8-Leads, Body 4.9x3.8mm, Pitch 1.27mm, IPC High Density)
footprint SOIC-SN8_M (SOIC, 8-Leads, Body 4.9x3.8mm, Pitch 1.27mm, IPC Low Density)
pins: 1 ~{CS} (in), 2 SO (hiz), 3 ~{WP} (in), 4 VSS (power), 5 SI (in), 6 SCK (in), 7 ~{HOLD} (in), 8 VCC (power)

## 25LC160AT-I/ST
designator U?
16K SPI Bus Serial EEPROM, 8-Pin TSSOP, Industrial Temperature, Tape and Reel; ComponentAvailability: Unknown. Contact manufacturer to determine status.
footprint TSSOP-ST8_N (TSOP, 8-Leads, Body 3x4.4mm, Pitch 0.65mm, IPC Medium Density)
footprint TSSOP-ST8_L (TSOP, 8-Leads, Body 3x4.4mm, Pitch 0.65mm, IPC High Density)
footprint TSSOP-ST8_M (TSOP, 8-Leads, Body 3x4.4mm, Pitch 0.65mm, IPC Low Density)
pins: 1 ~{CS} (in), 2 SO (hiz), 3 ~{WP} (in), 4 VSS (power), 5 SI (in), 6 SCK (in), 7 ~{HOLD} (in), 8 VCC (power)

## 25LC160B-E/MS
designator U?
16K SPI Bus Serial EEPROM, 8-Pin MSOP, Extended Temperature; ComponentAvailability: Unknown. Contact manufacturer to determine status.
footprint MSOP-MS8_N (TSOP, 8-Leads, Body 3x3mm, Pitch 0.65mm, IPC Medium Density)
footprint MSOP-MS8_L (TSOP, 8-Leads, Body 3x3mm, Pitch 0.65mm, IPC High Density)
footprint MSOP-MS8_M (TSOP, 8-Leads, Body 3x3mm, Pitch 0.65mm, IPC Low Density)
pins: 1 ~{CS} (in), 2 SO (hiz), 3 ~{WP} (in), 4 VSS (power), 5 SI (in), 6 SCK (in), 7 ~{HOLD} (in), 8 VCC (power)

## 25LC160B-E/P
designator U?
16K SPI Bus Serial EEPROM, 8-Pin PDIP, Extended Temperature; ComponentAvailability: Unknown. Contact manufacturer to determine status.
footprint PDIP300-P8 (DIP, 8-Leads, Row Spacing 7.62mm, Pitch 2.54mm, Body 9.5x6.6mm)
pins: 1 ~{CS} (in), 2 SO (hiz), 3 ~{WP} (in), 4 VSS (power), 5 SI (in), 6 SCK (in), 7 ~{HOLD} (in), 8 VCC (power)

## 25LC160B-E/SN
designator U?
16K SPI Bus Serial EEPROM, 8-Pin SOIC, Extended Temperature; ComponentAvailability: Unknown. Contact manufacturer to determine status.
footprint SOIC-SN8_N (SOIC, 8-Leads, Body 4.9x3.8mm, Pitch 1.27mm, IPC Medium Density)
footprint SOIC-SN8_L (SOIC, 8-Leads, Body 4.9x3.8mm, Pitch 1.27mm, IPC High Density)
footprint SOIC-SN8_M (SOIC, 8-Leads, Body 4.9x3.8mm, Pitch 1.27mm, IPC Low Density)
pins: 1 ~{CS} (in), 2 SO (hiz), 3 ~{WP} (in), 4 VSS (power), 5 SI (in), 6 SCK (in), 7 ~{HOLD} (in), 8 VCC (power)

## 25LC160B-E/ST
designator U?
16K SPI Bus Serial EEPROM, 8-Pin TSSOP, Extended Temperature; ComponentAvailability: Unknown. Contact manufacturer to determine status.
footprint TSSOP-ST8_N (TSOP, 8-Leads, Body 3x4.4mm, Pitch 0.65mm, IPC Medium Density)
footprint TSSOP-ST8_L (TSOP, 8-Leads, Body 3x4.4mm, Pitch 0.65mm, IPC High Density)
footprint TSSOP-ST8_M (TSOP, 8-Leads, Body 3x4.4mm, Pitch 0.65mm, IPC Low Density)
pins: 1 ~{CS} (in), 2 SO (hiz), 3 ~{WP} (in), 4 VSS (power), 5 SI (in), 6 SCK (in), 7 ~{HOLD} (in), 8 VCC (power)

## 25LC160B-I/MS
designator U?
16K SPI Bus Serial EEPROM, 8-Pin MSOP, Industrial Temperature; ComponentAvailability: Unknown. Contact manufacturer to determine status.
footprint MSOP-MS8_N (TSOP, 8-Leads, Body 3x3mm, Pitch 0.65mm, IPC Medium Density)
footprint MSOP-MS8_L (TSOP, 8-Leads, Body 3x3mm, Pitch 0.65mm, IPC High Density)
footprint MSOP-MS8_M (TSOP, 8-Leads, Body 3x3mm, Pitch 0.65mm, IPC Low Density)
pins: 1 ~{CS} (in), 2 SO (hiz), 3 ~{WP} (in), 4 VSS (power), 5 SI (in), 6 SCK (in), 7 ~{HOLD} (in), 8 VCC (power)

## 25LC160B-I/P
designator U?
16K SPI Bus Serial EEPROM, 8-Pin PDIP, Industrial Temperature; ComponentAvailability: Unknown. Contact manufacturer to determine status.
footprint PDIP300-P8 (DIP, 8-Leads, Row Spacing 7.62mm, Pitch 2.54mm, Body 9.5x6.6mm)
pins: 1 ~{CS} (in), 2 SO (hiz), 3 ~{WP} (in), 4 VSS (power), 5 SI (in), 6 SCK (in), 7 ~{HOLD} (in), 8 VCC (power)

## 25LC160B-I/SN
designator U?
16K SPI Bus Serial EEPROM, 8-Pin SOIC, Industrial Temperature; ComponentAvailability: Unknown. Contact manufacturer to determine status.
footprint SOIC-SN8_N (SOIC, 8-Leads, Body 4.9x3.8mm, Pitch 1.27mm, IPC Medium Density)
footprint SOIC-SN8_L (SOIC, 8-Leads, Body 4.9x3.8mm, Pitch 1.27mm, IPC High Density)
footprint SOIC-SN8_M (SOIC, 8-Leads, Body 4.9x3.8mm, Pitch 1.27mm, IPC Low Density)
pins: 1 ~{CS} (in), 2 SO (hiz), 3 ~{WP} (in), 4 VSS (power), 5 SI (in), 6 SCK (in), 7 ~{HOLD} (in), 8 VCC (power)

## 25LC160B-I/ST
designator U?
16K SPI Bus Serial EEPROM, 8-Pin TSSOP, Industrial Temperature; ComponentAvailability: Unknown. Contact manufacturer to determine status.
footprint TSSOP-ST8_N (TSOP, 8-Leads, Body 3x4.4mm, Pitch 0.65mm, IPC Medium Density)
footprint TSSOP-ST8_L (TSOP, 8-Leads, Body 3x4.4mm, Pitch 0.65mm, IPC High Density)
footprint TSSOP-ST8_M (TSOP, 8-Leads, Body 3x4.4mm, Pitch 0.65mm, IPC Low Density)
pins: 1 ~{CS} (in), 2 SO (hiz), 3 ~{WP} (in), 4 VSS (power), 5 SI (in), 6 SCK (in), 7 ~{HOLD} (in), 8 VCC (power)

## 25LC160BT-E/MS
designator U?
16K SPI Bus Serial EEPROM, 8-Pin MSOP, Extended Temperature, Tape and Reel; ComponentAvailability: Unknown. Contact manufacturer to determine status.
footprint MSOP-MS8_N (TSOP, 8-Leads, Body 3x3mm, Pitch 0.65mm, IPC Medium Density)
footprint MSOP-MS8_L (TSOP, 8-Leads, Body 3x3mm, Pitch 0.65mm, IPC High Density)
footprint MSOP-MS8_M (TSOP, 8-Leads, Body 3x3mm, Pitch 0.65mm, IPC Low Density)
pins: 1 ~{CS} (in), 2 SO (hiz), 3 ~{WP} (in), 4 VSS (power), 5 SI (in), 6 SCK (in), 7 ~{HOLD} (in), 8 VCC (power)

## 25LC160BT-E/SN
designator U?
16K SPI Bus Serial EEPROM, 8-Pin SOIC, Extended Temperature, Tape and Reel; ComponentAvailability: Unknown. Contact manufacturer to determine status.
footprint SOIC-SN8_N (SOIC, 8-Leads, Body 4.9x3.8mm, Pitch 1.27mm, IPC Medium Density)
footprint SOIC-SN8_L (SOIC, 8-Leads, Body 4.9x3.8mm, Pitch 1.27mm, IPC High Density)
footprint SOIC-SN8_M (SOIC, 8-Leads, Body 4.9x3.8mm, Pitch 1.27mm, IPC Low Density)
pins: 1 ~{CS} (in), 2 SO (hiz), 3 ~{WP} (in), 4 VSS (power), 5 SI (in), 6 SCK (in), 7 ~{HOLD} (in), 8 VCC (power)

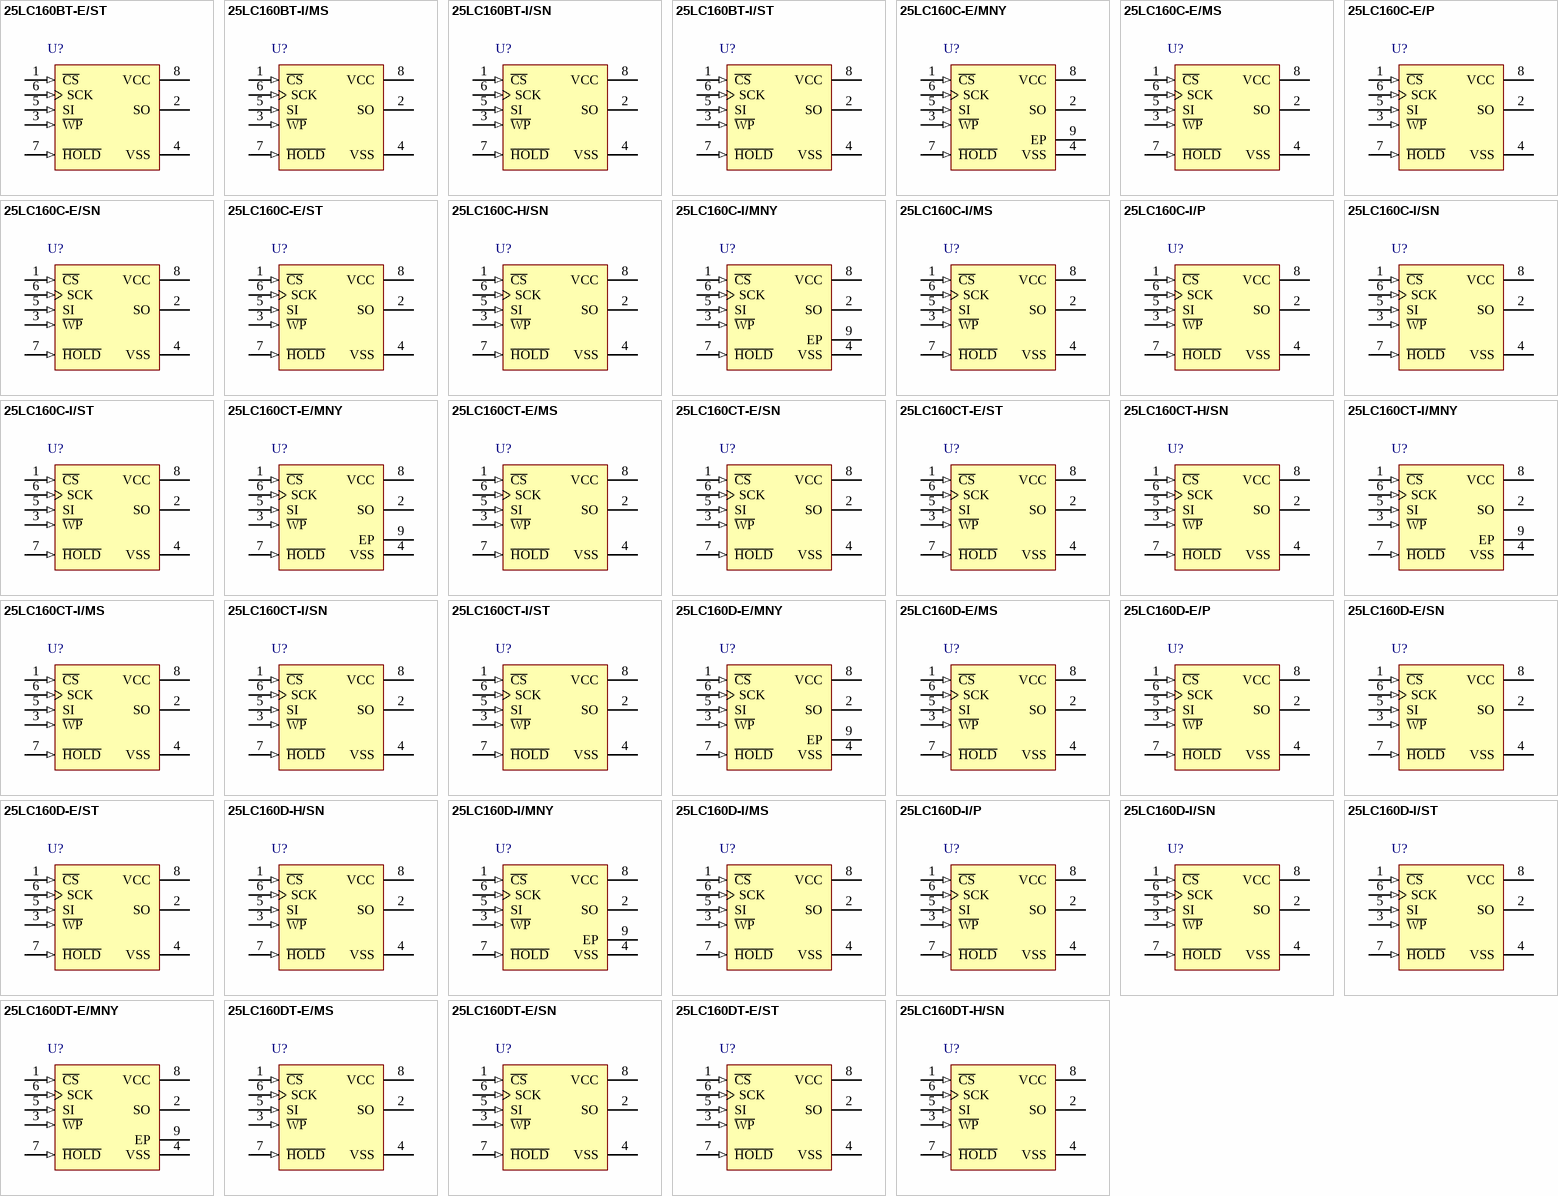
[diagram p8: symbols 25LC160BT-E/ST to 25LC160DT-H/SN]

## 25LC160BT-E/ST
designator U?
16K SPI Bus Serial EEPROM, 8-Pin TSSOP, Extended Temperature, Tape and Reel; ComponentAvailability: Unknown. Contact manufacturer to determine status.
footprint TSSOP-ST8_N (TSOP, 8-Leads, Body 3x4.4mm, Pitch 0.65mm, IPC Medium Density)
footprint TSSOP-ST8_L (TSOP, 8-Leads, Body 3x4.4mm, Pitch 0.65mm, IPC High Density)
footprint TSSOP-ST8_M (TSOP, 8-Leads, Body 3x4.4mm, Pitch 0.65mm, IPC Low Density)
pins: 1 ~{CS} (in), 2 SO (hiz), 3 ~{WP} (in), 4 VSS (power), 5 SI (in), 6 SCK (in), 7 ~{HOLD} (in), 8 VCC (power)

## 25LC160BT-I/MS
designator U?
16K SPI Bus Serial EEPROM, 8-Pin MSOP, Industrial Temperature, Tape and Reel; ComponentAvailability: Unknown. Contact manufacturer to determine status.
footprint MSOP-MS8_N (TSOP, 8-Leads, Body 3x3mm, Pitch 0.65mm, IPC Medium Density)
footprint MSOP-MS8_L (TSOP, 8-Leads, Body 3x3mm, Pitch 0.65mm, IPC High Density)
footprint MSOP-MS8_M (TSOP, 8-Leads, Body 3x3mm, Pitch 0.65mm, IPC Low Density)
pins: 1 ~{CS} (in), 2 SO (hiz), 3 ~{WP} (in), 4 VSS (power), 5 SI (in), 6 SCK (in), 7 ~{HOLD} (in), 8 VCC (power)

## 25LC160BT-I/SN
designator U?
16K SPI Bus Serial EEPROM, 8-Pin SOIC, Industrial Temperature, Tape and Reel; ComponentAvailability: Unknown. Contact manufacturer to determine status.
footprint SOIC-SN8_N (SOIC, 8-Leads, Body 4.9x3.8mm, Pitch 1.27mm, IPC Medium Density)
footprint SOIC-SN8_L (SOIC, 8-Leads, Body 4.9x3.8mm, Pitch 1.27mm, IPC High Density)
footprint SOIC-SN8_M (SOIC, 8-Leads, Body 4.9x3.8mm, Pitch 1.27mm, IPC Low Density)
pins: 1 ~{CS} (in), 2 SO (hiz), 3 ~{WP} (in), 4 VSS (power), 5 SI (in), 6 SCK (in), 7 ~{HOLD} (in), 8 VCC (power)

## 25LC160BT-I/ST
designator U?
16K SPI Bus Serial EEPROM, 8-Pin TSSOP, Industrial Temperature, Tape and Reel; ComponentAvailability: Unknown. Contact manufacturer to determine status.
footprint TSSOP-ST8_N (TSOP, 8-Leads, Body 3x4.4mm, Pitch 0.65mm, IPC Medium Density)
footprint TSSOP-ST8_L (TSOP, 8-Leads, Body 3x4.4mm, Pitch 0.65mm, IPC High Density)
footprint TSSOP-ST8_M (TSOP, 8-Leads, Body 3x4.4mm, Pitch 0.65mm, IPC Low Density)
pins: 1 ~{CS} (in), 2 SO (hiz), 3 ~{WP} (in), 4 VSS (power), 5 SI (in), 6 SCK (in), 7 ~{HOLD} (in), 8 VCC (power)

## 25LC160C-E/MNY
designator U?
16K SPI Bus Serial EEPROM, 8-Pin TDFN, Automotive Temperature
footprint TDFN-MN8 (SON, 8-Leads, Body 2x3mm, Pitch 0.5mm, Microchip Recommended)
pins: 1 ~{CS} (in), 2 SO (hiz), 3 ~{WP} (in), 4 VSS (power), 5 SI (in), 6 SCK (in), 7 ~{HOLD} (in), 8 VCC (power), 9 EP

## 25LC160C-E/MS
designator U?
16K SPI Bus Serial EEPROM, 8-Pin MSOP, Automotive Temperature
footprint MSOP-MS8_N (TSOP, 8-Leads, Body 3x3mm, Pitch 0.65mm, IPC Medium Density)
footprint MSOP-MS8_L (TSOP, 8-Leads, Body 3x3mm, Pitch 0.65mm, IPC High Density)
footprint MSOP-MS8_M (TSOP, 8-Leads, Body 3x3mm, Pitch 0.65mm, IPC Low Density)
pins: 1 ~{CS} (in), 2 SO (hiz), 3 ~{WP} (in), 4 VSS (power), 5 SI (in), 6 SCK (in), 7 ~{HOLD} (in), 8 VCC (power)

## 25LC160C-E/P
designator U?
16K SPI Bus Serial EEPROM, 8-Pin PDIP, Automotive Temperature
footprint PDIP300-P8 (DIP, 8-Leads, Row Spacing 7.62mm, Pitch 2.54mm, Body 9.5x6.6mm)
pins: 1 ~{CS} (in), 2 SO (hiz), 3 ~{WP} (in), 4 VSS (power), 5 SI (in), 6 SCK (in), 7 ~{HOLD} (in), 8 VCC (power)

## 25LC160C-E/SN
designator U?
16K SPI Bus Serial EEPROM, 8-Pin SOIC, Automotive Temperature
footprint SOIC-SN8_N (SOIC, 8-Leads, Body 4.9x3.8mm, Pitch 1.27mm, IPC Medium Density)
footprint SOIC-SN8_L (SOIC, 8-Leads, Body 4.9x3.8mm, Pitch 1.27mm, IPC High Density)
footprint SOIC-SN8_M (SOIC, 8-Leads, Body 4.9x3.8mm, Pitch 1.27mm, IPC Low Density)
pins: 1 ~{CS} (in), 2 SO (hiz), 3 ~{WP} (in), 4 VSS (power), 5 SI (in), 6 SCK (in), 7 ~{HOLD} (in), 8 VCC (power)

## 25LC160C-E/ST
designator U?
16K SPI Bus Serial EEPROM, 8-Pin TSSO, Automotive Temperature
footprint TSSOP-ST8_N (TSOP, 8-Leads, Body 3x4.4mm, Pitch 0.65mm, IPC Medium Density)
footprint TSSOP-ST8_L (TSOP, 8-Leads, Body 3x4.4mm, Pitch 0.65mm, IPC High Density)
footprint TSSOP-ST8_M (TSOP, 8-Leads, Body 3x4.4mm, Pitch 0.65mm, IPC Low Density)
pins: 1 ~{CS} (in), 2 SO (hiz), 3 ~{WP} (in), 4 VSS (power), 5 SI (in), 6 SCK (in), 7 ~{HOLD} (in), 8 VCC (power)

## 25LC160C-H/SN
designator U?
16K SPI Bus Serial EEPROM, 8-Pin SOIC, Extended (High) Temperature
footprint SOIC-SN8_N (SOIC, 8-Leads, Body 4.9x3.8mm, Pitch 1.27mm, IPC Medium Density)
footprint SOIC-SN8_L (SOIC, 8-Leads, Body 4.9x3.8mm, Pitch 1.27mm, IPC High Density)
footprint SOIC-SN8_M (SOIC, 8-Leads, Body 4.9x3.8mm, Pitch 1.27mm, IPC Low Density)
pins: 1 ~{CS} (in), 2 SO (hiz), 3 ~{WP} (in), 4 VSS (power), 5 SI (in), 6 SCK (in), 7 ~{HOLD} (in), 8 VCC (power)

## 25LC160C-I/MNY
designator U?
16K SPI Bus Serial EEPROM, 8-Pin TDFN, Industrial Temperature
footprint TDFN-MN8 (SON, 8-Leads, Body 2x3mm, Pitch 0.5mm, Microchip Recommended)
pins: 1 ~{CS} (in), 2 SO (hiz), 3 ~{WP} (in), 4 VSS (power), 5 SI (in), 6 SCK (in), 7 ~{HOLD} (in), 8 VCC (power), 9 EP

## 25LC160C-I/MS
designator U?
16K SPI Bus Serial EEPROM, 8-Pin MSOP, Industrial Temperature
footprint MSOP-MS8_N (TSOP, 8-Leads, Body 3x3mm, Pitch 0.65mm, IPC Medium Density)
footprint MSOP-MS8_L (TSOP, 8-Leads, Body 3x3mm, Pitch 0.65mm, IPC High Density)
footprint MSOP-MS8_M (TSOP, 8-Leads, Body 3x3mm, Pitch 0.65mm, IPC Low Density)
pins: 1 ~{CS} (in), 2 SO (hiz), 3 ~{WP} (in), 4 VSS (power), 5 SI (in), 6 SCK (in), 7 ~{HOLD} (in), 8 VCC (power)

## 25LC160C-I/P
designator U?
16K SPI Bus Serial EEPROM, 8-Pin PDIP, Industrial Temperature
footprint PDIP300-P8 (DIP, 8-Leads, Row Spacing 7.62mm, Pitch 2.54mm, Body 9.5x6.6mm)
pins: 1 ~{CS} (in), 2 SO (hiz), 3 ~{WP} (in), 4 VSS (power), 5 SI (in), 6 SCK (in), 7 ~{HOLD} (in), 8 VCC (power)

## 25LC160C-I/SN
designator U?
16K SPI Bus Serial EEPROM, 8-Pin SOIC, Industrial Temperature
footprint SOIC-SN8_N (SOIC, 8-Leads, Body 4.9x3.8mm, Pitch 1.27mm, IPC Medium Density)
footprint SOIC-SN8_L (SOIC, 8-Leads, Body 4.9x3.8mm, Pitch 1.27mm, IPC High Density)
footprint SOIC-SN8_M (SOIC, 8-Leads, Body 4.9x3.8mm, Pitch 1.27mm, IPC Low Density)
pins: 1 ~{CS} (in), 2 SO (hiz), 3 ~{WP} (in), 4 VSS (power), 5 SI (in), 6 SCK (in), 7 ~{HOLD} (in), 8 VCC (power)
